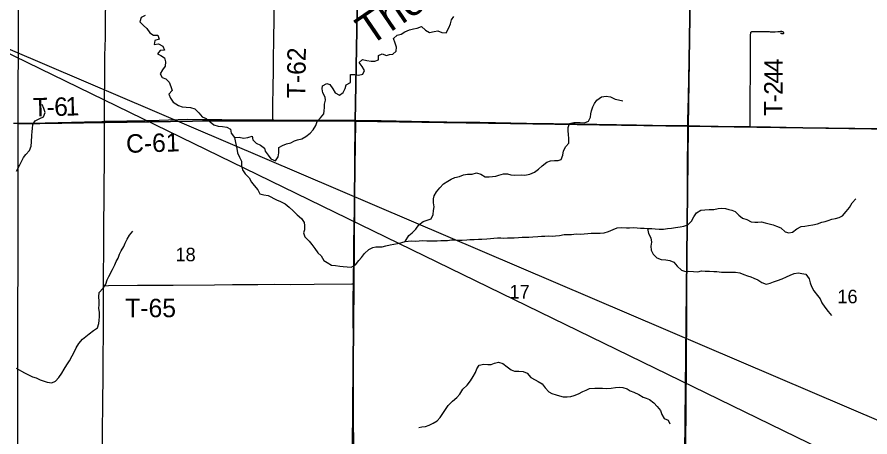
# Model space of a CAD drawing. Extents: x 0 to 45.9, y 0 to 22.
# Drawn here: x 5.48 to 8.107, y 16.738 to 18.033 of the extents above; entities that cross this region are included whole.
import ezdxf

# ---------------------------------------------------------------- set-up
doc = ezdxf.new("R2010")
doc.units = 0
for name, color, linetype in [('GM_X_County_Road', 7, 'Continuous'), ('GM_X_County_Road_Text', 7, 'Continuous'), ('GM_X_Minor_River', 7, 'Continuous'), ('GM_X_Minor_River_Text', 7, 'Continuous'), ('GM_X_Section', 7, 'Continuous'), ('GM_X_Section_Text', 7, 'Continuous'), ('GM_X_Township_Road', 7, 'Continuous'), ('GM_X_Township_Road_Text', 7, 'Continuous'), ('SH_Border', 7, 'Continuous')]:
    doc.layers.add(name, color=color, linetype=linetype)

msp = doc.modelspace()

# ---------------------------------------------------------------- linework, layer by layer
at = {"layer": 'GM_X_County_Road'}
for points in [[(7.5458, 17.698), (7.5463, 17.7142), (7.5476, 17.7856), (7.5486, 17.8446), (7.5508, 17.9503), (7.5522, 18.0404), (7.5541, 18.1211), (7.5547, 18.1615), (7.5549, 18.1832), (7.5556, 18.2174), (7.5564, 18.2516), (7.557, 18.2795), (7.5577, 18.3168), (7.5585, 18.3633), (7.5593, 18.4193), (7.5603, 18.469), (7.5612, 18.5152)], [(5.7497, 17.7112), (5.7632, 17.7119), (5.8185, 17.7129), (5.8744, 17.7139), (5.9179, 17.715), (6.0049, 17.7174), (6.0515, 17.717), (6.1105, 17.7168), (6.1726, 17.716), (6.2192, 17.7159), (6.2441, 17.7157), (6.2685, 17.7154)], [(6.2685, 17.7154), (6.2907, 17.7152), (6.3497, 17.7152), (6.415, 17.715), (6.4647, 17.715), (6.5237, 17.7143)], [(6.5237, 17.7143), (6.5485, 17.714), (6.6014, 17.7133), (6.6946, 17.7118), (6.8033, 17.7098), (6.9058, 17.7083), (7.0487, 17.706), (7.1326, 17.7045), (7.2662, 17.7021), (7.3874, 17.7006), (7.4868, 17.6985), (7.5458, 17.698)], [(7.5398, 16.6872), (7.5398, 16.695), (7.5401, 16.7448), (7.5405, 16.7976), (7.5408, 16.8255), (7.5412, 16.8721), (7.5414, 16.925), (7.5417, 16.9716), (7.5421, 17.0244), (7.5424, 17.0648), (7.5425, 17.1145), (7.543, 17.1829), (7.5432, 17.2077), (7.5434, 17.2792), (7.5436, 17.3382), (7.5438, 17.3693), (7.5443, 17.4097), (7.5448, 17.4625), (7.5452, 17.5153), (7.5452, 17.5681), (7.5461, 17.6707), (7.5458, 17.698)], [(7.5458, 17.698), (7.5831, 17.6971), (7.639, 17.6962), (7.726, 17.695), (7.738, 17.6948)], [(7.738, 17.6948), (7.8006, 17.6939), (7.8969, 17.6926), (8.1423, 17.6888), (8.1951, 17.6883), (8.2573, 17.6874), (8.3442, 17.6861), (8.4809, 17.6842), (8.536, 17.6836)]]:
    msp.add_lwpolyline(points, dxfattribs=at)
at = {"layer": 'GM_X_Minor_River'}
for points in [[(5.8752, 18.0375), (5.863, 18.0318), (5.8589, 18.0185), (5.8692, 18.0072), (5.8802, 17.997), (5.889, 17.9841), (5.9008, 17.9773), (5.9137, 17.977), (5.9175, 17.9641), (5.9046, 17.9602), (5.9024, 17.9481), (5.9157, 17.9497), (5.929, 17.9429), (5.9343, 17.9304), (5.9211, 17.9292), (5.9124, 17.9193), (5.9226, 17.914), (5.9344, 17.9073), (5.9371, 17.8951), (5.9364, 17.8815), (5.9285, 17.8697), (5.9206, 17.8575), (5.927, 17.8465), (5.9388, 17.842), (5.9491, 17.8318), (5.9537, 17.819), (5.9579, 17.8061), (5.9477, 17.795), (5.9531, 17.7825), (5.9615, 17.7701), (5.9774, 17.7595), (5.9888, 17.7557), (6.001, 17.7546), (6.0142, 17.7543), (6.0279, 17.7502), (6.0397, 17.7377), (6.05, 17.7252), (6.0625, 17.72), (6.0755, 17.7101), (6.0865, 17.7003), (6.0994, 17.6966), (6.1127, 17.6951), (6.126, 17.6929), (6.1378, 17.6872), (6.1393, 17.6743), (6.1504, 17.6618), (6.164, 17.6619), (6.1777, 17.6589), (6.1906, 17.6616), (6.2039, 17.6654), (6.2062, 17.6537), (6.2168, 17.6435), (6.2301, 17.6375), (6.2419, 17.6288), (6.2446, 17.6193), (6.2538, 17.6072), (6.2618, 17.5959), (6.2758, 17.5898), (6.2841, 17.602), (6.2864, 17.6145), (6.2867, 17.6305), (6.2973, 17.6369), (6.3105, 17.6419), (6.323, 17.645), (6.3348, 17.6507), (6.3443, 17.6542), (6.3571, 17.6569), (6.3693, 17.6641), (6.3825, 17.6752), (6.392, 17.6847), (6.4002, 17.6987)], [(6.4002, 17.6987), (6.4044, 17.7105), (6.415, 17.7219), (6.4255, 17.7341), (6.4263, 17.7436), (6.4266, 17.7534), (6.4266, 17.7637), (6.4303, 17.7766), (6.4295, 17.7861), (6.4223, 17.7989), (6.42, 17.8111), (6.4207, 17.8205), (6.4339, 17.8282), (6.4434, 17.8244), (6.4526, 17.8115), (6.4595, 17.7987), (6.4728, 17.7923), (6.4849, 17.8003), (6.4905, 17.8121), (6.4943, 17.8242), (6.5075, 17.8311), (6.5075, 17.8436), (6.5067, 17.8561), (6.52, 17.8554), (6.5321, 17.8535), (6.545, 17.857), (6.5503, 17.8684), (6.5434, 17.8801), (6.5342, 17.8926), (6.5441, 17.9014), (6.5577, 17.8984), (6.5703, 17.8965), (6.582, 17.8962), (6.593, 17.9012), (6.5933, 17.9144), (6.6051, 17.9198), (6.618, 17.9145), (6.6275, 17.9176), (6.637, 17.918), (6.6475, 17.9271), (6.6483, 17.94), (6.6444, 17.9522), (6.6391, 17.9662), (6.6508, 17.9768), (6.6629, 17.9799), (6.6747, 17.9871), (6.689, 17.9929), (6.7012, 17.996), (6.7129, 17.9983), (6.7262, 18.0033), (6.738, 17.9919), (6.7509, 17.9848), (6.7649, 17.9886), (6.7759, 17.9902), (6.7885, 17.9853), (6.8017, 17.9842), (6.8104, 17.999), (6.8153, 18.0115), (6.8183, 18.024), (6.8251, 18.0343)], [(6.6754, 17.3405), (6.6864, 17.3595), (6.6966, 17.3675), (6.7087, 17.3782), (6.7173, 17.3919), (6.731, 17.4021), (6.7435, 17.406), (6.7556, 17.4102), (6.7612, 17.4235), (6.7631, 17.4364), (6.765, 17.4474), (6.7623, 17.4599), (6.7626, 17.4724), (6.7652, 17.4819), (6.7724, 17.4937), (6.7822, 17.5059), (6.7935, 17.5188), (6.8068, 17.5272), (6.8174, 17.5325), (6.8284, 17.5375), (6.8424, 17.5413), (6.8549, 17.5467), (6.8678, 17.5486), (6.8818, 17.5487), (6.8947, 17.5525), (6.9084, 17.548), (6.9217, 17.5401), (6.9346, 17.5398), (6.9441, 17.5409), (6.9543, 17.5417), (6.9638, 17.5448), (6.9778, 17.549), (6.9907, 17.5494), (7.0013, 17.5464), (7.0123, 17.5457), (7.0339, 17.5458), (7.0442, 17.5454), (7.059, 17.5478), (7.0738, 17.5543), (7.0859, 17.5634), (7.0972, 17.5741), (7.1116, 17.5855), (7.1226, 17.5893), (7.1351, 17.5905), (7.1465, 17.5905), (7.1563, 17.5932), (7.1612, 17.6065), (7.1627, 17.6198), (7.1706, 17.6331), (7.18, 17.6441), (7.18, 17.6582), (7.1788, 17.671), (7.1776, 17.6824), (7.1776, 17.6919), (7.1817, 17.7041), (7.1946, 17.7079), (7.2045, 17.7079), (7.2143, 17.7072), (7.228, 17.7061), (7.2405, 17.7115), (7.2458, 17.724), (7.2476, 17.7342), (7.2495, 17.7437), (7.2532, 17.7563), (7.2589, 17.7658), (7.2661, 17.7764), (7.2801, 17.7867), (7.2945, 17.789), (7.3077, 17.7872), (7.3218, 17.78), (7.3324, 17.7774), (7.3453, 17.7744)], [(5.479, 17.5575), (5.4887, 17.5766), (5.4944, 17.5872), (5.5004, 17.5994), (5.5076, 17.6089), (5.5189, 17.6214), (5.5238, 17.6343), (5.5249, 17.648), (5.5256, 17.6677), (5.5267, 17.6795), (5.5278, 17.689), (5.5289, 17.7015), (5.5364, 17.7129), (5.55, 17.7197), (5.5622, 17.7255), (5.5667, 17.738), (5.5628, 17.7505), (5.5575, 17.7626)], [(6.1504, 17.6618), (6.1531, 17.6459), (6.157, 17.627), (6.1593, 17.6137), (6.165, 17.6012), (6.1711, 17.588), (6.1716, 17.5743), (6.1746, 17.5614), (6.1826, 17.5489), (6.1952, 17.5365), (6.2021, 17.524), (6.2108, 17.513), (6.2215, 17.5001), (6.2284, 17.4873), (6.2405, 17.4843), (6.2531, 17.4824), (6.2789, 17.4696), (6.2914, 17.4636), (6.3063, 17.4564), (6.3181, 17.4466), (6.3302, 17.4353), (6.3428, 17.4228), (6.3565, 17.4111), (6.3649, 17.399), (6.3653, 17.3895), (6.365, 17.3766), (6.3627, 17.3671), (6.3662, 17.3546), (6.3803, 17.3418), (6.3879, 17.3319), (6.397, 17.3195), (6.4066, 17.3062), (6.4172, 17.296), (6.4252, 17.2824), (6.4348, 17.2756), (6.4484, 17.2677), (6.461, 17.2666), (6.4746, 17.2651), (6.4841, 17.264), (6.497, 17.2625), (6.5095, 17.2614), (6.5224, 17.2687), (6.5326, 17.2816), (6.5409, 17.2911), (6.55, 17.3033), (6.5636, 17.3162), (6.5757, 17.322), (6.5852, 17.3247), (6.5947, 17.3239), (6.6049, 17.3247), (6.6159, 17.327), (6.6296, 17.3305), (6.6405, 17.3321), (6.6515, 17.3344), (6.6648, 17.3374), (6.6754, 17.3405), (6.6849, 17.3417), (6.6944, 17.3425), (6.7073, 17.3418), (6.7187, 17.3429), (6.7304, 17.3434), (6.7418, 17.3423), (6.7513, 17.3431), (6.774, 17.3431), (6.785, 17.3435), (6.7945, 17.344), (6.8055, 17.344), (6.8184, 17.3459), (6.8294, 17.3456), (6.8389, 17.3452), (6.851, 17.3449), (6.8655, 17.3453), (6.8749, 17.3465), (6.8878, 17.3473), (6.9015, 17.3477), (6.9114, 17.3478), (6.9265, 17.3486), (6.9383, 17.3494), (6.9489, 17.3513), (6.9603, 17.3517), (6.9701, 17.3521), (6.9796, 17.3514), (6.991, 17.3515), (7.0009, 17.3519), (7.0115, 17.3523), (7.0244, 17.3535), (7.0358, 17.3539), (7.046, 17.3539), (7.0559, 17.3543), (7.0691, 17.3551), (7.0843, 17.3559), (7.0949, 17.3571), (7.1056, 17.3575), (7.1158, 17.3579), (7.1291, 17.3576), (7.1389, 17.3584), (7.1511, 17.3596), (7.1655, 17.3619), (7.1753, 17.3623), (7.1875, 17.3627), (7.2019, 17.3639)], [(7.2019, 17.3639), (7.214, 17.3632), (7.2265, 17.3648), (7.2383, 17.3656), (7.2485, 17.366), (7.2626, 17.3664), (7.2755, 17.3668), (7.2884, 17.3676), (7.302, 17.3715), (7.3156, 17.3772), (7.3281, 17.3826), (7.3422, 17.3837), (7.3566, 17.3827), (7.3661, 17.3831), (7.379, 17.3835), (7.3896, 17.3831), (7.4006, 17.382), (7.4112, 17.3813), (7.4218, 17.381), (7.4351, 17.3803), (7.4457, 17.3795), (7.4579, 17.3792), (7.4715, 17.3792), (7.4829, 17.3808), (7.4958, 17.382), (7.5083, 17.3839), (7.522, 17.3859), (7.5341, 17.3878), (7.5462, 17.392), (7.5568, 17.4034), (7.564, 17.4163), (7.5726, 17.4293), (7.5855, 17.4369), (7.5984, 17.4385), (7.6121, 17.4389), (7.6257, 17.4397), (7.639, 17.4428), (7.6492, 17.4439), (7.6621, 17.4421), (7.6724, 17.4395), (7.6819, 17.4372), (7.6921, 17.4331), (7.7028, 17.4214), (7.7146, 17.413), (7.7279, 17.4089), (7.7412, 17.4018), (7.7522, 17.3999), (7.7617, 17.3999), (7.773, 17.4011), (7.7837, 17.3981), (7.7962, 17.3947), (7.8083, 17.3925), (7.8194, 17.388), (7.8319, 17.3831), (7.846, 17.3703), (7.8566, 17.3673), (7.868, 17.3699), (7.8812, 17.3795), (7.8952, 17.3871), (7.9062, 17.3879), (7.9176, 17.3895), (7.9309, 17.3922), (7.9457, 17.3952), (7.9585, 17.3998), (7.9688, 17.4025), (7.9782, 17.4056), (7.9896, 17.4094), (8.0002, 17.4117), (8.012, 17.4144), (8.0222, 17.4194), (8.0335, 17.4335), (8.0437, 17.446), (8.0524, 17.4597), (8.0633, 17.4726)], [(5.4772, 16.9504), (5.5035, 16.9353), (5.5157, 16.9296), (5.5282, 16.9236), (5.5388, 16.9199), (5.5518, 16.9142), (5.5639, 16.9097), (5.5734, 16.9071), (5.5871, 16.9049), (5.5988, 16.9102), (5.609, 16.9212), (5.6185, 16.9342), (5.6256, 16.9467), (5.6339, 16.9608), (5.6422, 16.9725), (5.6505, 16.9881), (5.6565, 16.9999), (5.6622, 17.0132), (5.6705, 17.0265), (5.6822, 17.0394), (5.692, 17.0482), (5.7019, 17.0558), (5.7155, 17.0661), (5.728, 17.0741), (5.7321, 17.0874), (5.7336, 17.0969), (5.7347, 17.1094), (5.7342, 17.1219), (5.7323, 17.1352), (5.733, 17.145), (5.733, 17.1568), (5.7326, 17.1704), (5.7333, 17.1837), (5.7454, 17.1967), (5.7533, 17.2096), (5.7582, 17.2225), (5.7634, 17.2327), (5.7744, 17.2548), (5.7811, 17.2692), (5.786, 17.2791), (5.7917, 17.289), (5.7962, 17.3015), (5.8007, 17.3118), (5.809, 17.3254), (5.8135, 17.3353), (5.8199, 17.3478), (5.8267, 17.3604), (5.8369, 17.3726)], [(7.4218, 17.381), (7.4253, 17.3651), (7.4322, 17.3518), (7.4345, 17.3389), (7.4319, 17.3264), (7.4327, 17.3143), (7.4396, 17.3014), (7.4506, 17.2904), (7.4639, 17.2848), (7.4787, 17.2837), (7.4905, 17.2818), (7.5026, 17.2766), (7.5129, 17.2641), (7.5262, 17.252), (7.5391, 17.2479), (7.5494, 17.2487), (7.5638, 17.2483), (7.5767, 17.2476), (7.5885, 17.2499), (7.5998, 17.2496), (7.6124, 17.2496), (7.626, 17.2485), (7.6355, 17.2482), (7.6492, 17.2463), (7.6586, 17.2456), (7.6932, 17.2457), (7.7057, 17.2443), (7.7182, 17.2394), (7.7296, 17.2345), (7.7395, 17.2322), (7.749, 17.2281), (7.7611, 17.2228), (7.7737, 17.2145), (7.787, 17.2096), (7.7999, 17.2123), (7.8097, 17.2165), (7.8222, 17.2204), (7.8362, 17.2253), (7.8495, 17.2315), (7.8609, 17.2368), (7.8737, 17.2418), (7.887, 17.2437), (7.8965, 17.2422), (7.9094, 17.2396), (7.9193, 17.2252), (7.9224, 17.2127), (7.9266, 17.2021), (7.9342, 17.1885), (7.9449, 17.1745), (7.9533, 17.1643), (7.959, 17.1514), (7.9674, 17.1385), (7.9781, 17.1249), (7.9884, 17.1128)], [(6.7177, 16.7676), (6.7271, 16.7692), (6.7378, 16.7707), (6.7495, 16.7745), (6.762, 16.7806), (6.7745, 16.7879), (6.7832, 16.7978), (6.7919, 16.8103), (6.8002, 16.8229), (6.8077, 16.8354), (6.8209, 16.8487), (6.8342, 16.8598), (6.844, 16.8704), (6.8534, 16.8849), (6.8659, 16.8974), (6.8765, 16.9107), (6.8844, 16.924), (6.8916, 16.937), (6.8957, 16.9476), (6.9036, 16.9594), (6.9176, 16.9628), (6.9302, 16.9614), (6.9408, 16.9618), (6.9506, 16.9656), (6.9632, 16.9683), (6.9761, 16.9642), (6.9894, 16.9544), (7.0023, 16.9453), (7.0122, 16.9412), (7.0258, 16.9405), (7.0391, 16.9401), (7.0509, 16.9345), (7.0627, 16.9216), (7.076, 16.9137), (7.0855, 16.9092), (7.0973, 16.9013), (7.1068, 16.8891), (7.1175, 16.8774), (7.1274, 16.8722), (7.1403, 16.8676), (7.1505, 16.8646), (7.1619, 16.8616), (7.1741, 16.8613), (7.1854, 16.8632), (7.1964, 16.8659), (7.2097, 16.8713), (7.2226, 16.8778), (7.2324, 16.8824), (7.2434, 16.8873), (7.2597, 16.8885), (7.2737, 16.8886), (7.2836, 16.8882), (7.2957, 16.8871), (7.3098, 16.8887), (7.3227, 16.8903), (7.3356, 16.8914), (7.3454, 16.8907), (7.3587, 16.8862), (7.3686, 16.8802), (7.3792, 16.8757), (7.3948, 16.8689), (7.4081, 16.8606), (7.418, 16.8576), (7.4275, 16.8531), (7.4412, 16.8436), (7.4518, 16.8323), (7.4618, 16.8194), (7.4663, 16.8073), (7.4732, 16.7952), (7.4854, 16.7895), (7.4907, 16.7782)]]:
    msp.add_lwpolyline(points, dxfattribs=at)
at = {"layer": 'GM_X_Section'}
for points in [[(5.4871, 18.7066), (6.0626, 18.725), (6.54, 18.7231), (6.5217, 17.7114), (6.0871, 17.7131), (5.4835, 17.7031)], [(6.54, 18.7231), (7.5622, 18.7071), (7.5472, 17.6966), (6.5217, 17.7114)], [(7.5622, 18.7071), (8.5306, 18.6937), (8.5357, 17.6824), (7.5472, 17.6966)], [(5.4835, 17.7031), (6.0871, 17.7131), (6.5217, 17.7114), (6.5134, 16.7036), (5.9766, 16.7084), (5.4822, 16.699)], [(6.5217, 17.7114), (7.5472, 17.6966), (7.5363, 16.6862), (6.5134, 16.7036)], [(7.5472, 17.6966), (8.5357, 17.6824), (8.5339, 16.6685), (7.5363, 16.6862)]]:
    msp.add_lwpolyline(points, close=True, dxfattribs=at)
at = {"layer": 'GM_X_Township_Road'}
for points in [[(5.7497, 17.7112), (5.75, 17.7565), (5.7507, 17.8653), (5.7509, 17.915), (5.7514, 17.9398), (5.7522, 17.9709), (5.7527, 18.0268), (5.7534, 18.0796), (5.754, 18.1293), (5.7544, 18.1666), (5.7545, 18.2288), (5.7549, 18.2723), (5.755, 18.3251), (5.7556, 18.3624), (5.7563, 18.4183), (5.7563, 18.4431), (5.7567, 18.4742), (5.7573, 18.527), (5.7577, 18.5612), (5.7579, 18.6016), (5.7582, 18.6327), (5.7587, 18.701), (5.7587, 18.7103), (5.7587, 18.7155)], [(6.2684, 17.7593), (6.2691, 17.8188), (6.2699, 17.8653), (6.2704, 17.9026), (6.2713, 17.9647), (6.2723, 18.0268), (6.2736, 18.0889), (6.2747, 18.1603), (6.2757, 18.2224), (6.2773, 18.3187), (6.2787, 18.3839), (6.2801, 18.4615), (6.281, 18.4957), (6.2815, 18.5146)], [(7.738, 17.6948), (7.738, 17.7002), (7.738, 17.7623), (7.7389, 17.8835), (7.7391, 17.9301), (7.7392, 17.9736), (7.7393, 17.9778)], [(7.7393, 17.9778), (7.7395, 17.9829), (7.7404, 17.9859), (7.7428, 17.9878), (7.7458, 17.9886), (7.7582, 17.9885), (7.7637, 17.9886), (7.7719, 17.9886), (7.7888, 17.9881), (7.7964, 17.9877), (7.7998, 17.9876), (7.8148, 17.9876), (7.8235, 17.9878), (7.8261, 17.9878), (7.829, 17.9884), (7.832, 17.9888), (7.833, 17.9888), (7.8341, 17.9888), (7.835, 17.9888), (7.8359, 17.9887), (7.8369, 17.9885), (7.8378, 17.9881), (7.8387, 17.9878), (7.8393, 17.9873), (7.8398, 17.9868), (7.8405, 17.9856), (7.8405, 17.9848), (7.8406, 17.9839), (7.8406, 17.9832), (7.8401, 17.9818), (7.8395, 17.9812), (7.8387, 17.9809), (7.8378, 17.9809), (7.8367, 17.9809), (7.836, 17.9811), (7.8352, 17.9813), (7.834, 17.9818), (7.8333, 17.9822), (7.8327, 17.9826), (7.8316, 17.9837), (7.8311, 17.9844)], [(6.2685, 17.7154), (6.2683, 17.7194), (6.2681, 17.7225), (6.2682, 17.7411), (6.2684, 17.7593)], [(5.4696, 17.7055), (5.5009, 17.7053), (5.5666, 17.7064), (5.6884, 17.7097), (5.7415, 17.711), (5.7497, 17.7112)], [(5.7469, 17.2044), (5.747, 17.2438), (5.7473, 17.306), (5.7477, 17.3526), (5.7479, 17.393), (5.7483, 17.4738), (5.7486, 17.5204), (5.7491, 17.5794), (5.7496, 17.6509), (5.7496, 17.7006), (5.7497, 17.7112)], [(5.7497, 17.7112), (5.7632, 17.7119), (5.8185, 17.7129), (5.8744, 17.7139), (5.9179, 17.715), (6.0049, 17.7174), (6.0515, 17.717), (6.1105, 17.7168), (6.1726, 17.716), (6.2192, 17.7159), (6.2441, 17.7157), (6.2685, 17.7154)], [(6.2685, 17.7154), (6.2907, 17.7152), (6.3497, 17.7152), (6.415, 17.715), (6.4647, 17.715), (6.5237, 17.7143)], [(6.5172, 16.7037), (6.5172, 16.7187), (6.5168, 16.7871), (6.5162, 16.8586), (6.516, 17.0047), (6.516, 17.0544), (6.5154, 17.0917), (6.5158, 17.1135), (6.5158, 17.1321), (6.5155, 17.1445), (6.5154, 17.1694), (6.5162, 17.2066), (6.5163, 17.2101), (6.5164, 17.2377), (6.5169, 17.2781), (6.5179, 17.3403), (6.5183, 17.3807), (6.5196, 17.4491), (6.5211, 17.5673), (6.5223, 17.6419), (6.5236, 17.7071), (6.5237, 17.7143)], [(6.5237, 17.7143), (6.5485, 17.714), (6.6014, 17.7133), (6.6946, 17.7118), (6.8033, 17.7098), (6.9058, 17.7083), (7.0487, 17.706), (7.1326, 17.7045), (7.2662, 17.7021), (7.3874, 17.7006), (7.4868, 17.6985), (7.5458, 17.698)], [(7.5458, 17.698), (7.5831, 17.6971), (7.639, 17.6962), (7.726, 17.695), (7.738, 17.6948)], [(7.738, 17.6948), (7.8006, 17.6939), (7.8969, 17.6926), (8.1423, 17.6888), (8.1951, 17.6883), (8.2573, 17.6874), (8.3442, 17.6861), (8.4809, 17.6842), (8.536, 17.6836)], [(5.7436, 16.7061), (5.7436, 16.728), (5.7435, 16.7529), (5.7438, 16.7809), (5.7443, 16.815), (5.7449, 16.8647), (5.7453, 16.9051), (5.7458, 16.9611), (5.746, 17.0015), (5.7462, 17.0387), (5.7465, 17.0947), (5.7468, 17.1537), (5.7468, 17.1879), (5.7469, 17.2044)], [(5.7469, 17.2044), (5.7507, 17.2044), (5.7615, 17.2045), (5.8517, 17.2055), (5.9607, 17.2062), (6.0883, 17.2073), (6.144, 17.2082), (6.1936, 17.2079), (6.2214, 17.2081), (6.2742, 17.209), (6.321, 17.2085), (6.3957, 17.2089), (6.5109, 17.21), (6.5163, 17.2101)]]:
    msp.add_lwpolyline(points, dxfattribs=at)
at = {"layer": 'SH_Border'}
msp.add_lwpolyline([(9.4963, 16.2045), (5.2331, 18.0284), (9.4963, 15.9502)], close=True, dxfattribs=at)

# ---------------------------------------------------------------- texts
at = {"layer": 'GM_X_County_Road_Text'}
msp.add_text('C-61', height=0.05682, rotation=1.7185, dxfattribs=at).set_placement((5.8168, 17.6138))
at = {"layer": 'GM_X_Minor_River_Text'}
msp.add_text('Thorn', height=0.09472, rotation=34.3127, dxfattribs=at).set_placement((6.5666, 17.9416))
at = {"layer": 'GM_X_Section_Text'}
for s, p in [('18', (5.9681, 17.2796)), ('17', (6.9968, 17.1648)), ('16', (8.0064, 17.1501))]:
    msp.add_text(s, height=0.04186, rotation=0, dxfattribs=at).set_placement(p)
at = {"layer": 'GM_X_Township_Road_Text'}
for s, height, rotation, p in [('T-62', 0.05682, 89.2934, (6.3679, 17.7823)), ('4', 0.0568, 89.7543, (7.8379, 17.8624)), ('4', 0.0568, 89.7346, (7.8377, 17.8276)), ('2', 0.0568, 89.7237, (7.8376, 17.7929)), ('T', 0.0568, 1.1218, (5.5294, 17.7262)), ('6', 0.0568, 1.497, (5.5953, 17.7276)), ('1', 0.0568, 1.5109, (5.6301, 17.7285)), ('-', 0.0568, 89.7203, (7.8375, 17.7698)), ('T', 0.0568, 89.719, (7.8373, 17.7274)), ('-', 0.0568, 1.3943, (5.5721, 17.727)), ('T-65', 0.05682, 0, (5.8135, 17.1072))]:
    msp.add_text(s, height=height, rotation=rotation, dxfattribs=at).set_placement(p)

doc.saveas('drawing.dxf')
